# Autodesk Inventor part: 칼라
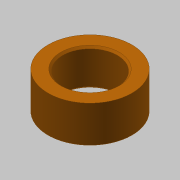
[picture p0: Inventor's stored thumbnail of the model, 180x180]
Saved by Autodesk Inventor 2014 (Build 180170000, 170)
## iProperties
Created: 2015-09
Part Number: 칼라
Document SubType Name: Modeling
Designer: mduedu
Density: 1 g/cm^3
Material: 스테인리스강
Appearance: Orange
Author: mduedu
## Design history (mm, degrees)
node "작업 평면1"
node "작업 평면2"
sketch "스케치1"
  geometry: C1 r 7.5 at (0, 0); C2 r 11.5 at (0, 0); 1 further point
  constraints: 2 centre point, 2 coincident
  dimensions: "d0" = 15 diameter of C1; "d1" = 23 diameter of C2
extrude "돌출1" new body sketch "스케치1" stored distance "d2" = 9.85; taper "d3" = 0 deg
chamfer "모따기1" distance "d4" = 0.5; stored, may be unused: second distance "d5" = 2, angle "d6" = 45 deg
node "솔리드1"
